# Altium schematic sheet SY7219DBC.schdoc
size 127 x 101 mm
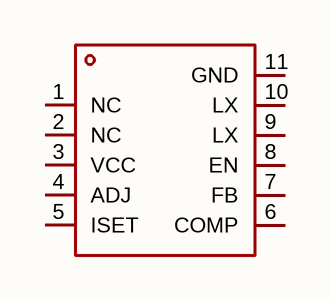
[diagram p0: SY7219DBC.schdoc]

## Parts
U?  sy7219dbc  [DFN-10_L3.0-W3.0-P0.50-TL-EP2.4]  (value not drawn)

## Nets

Not connected (* = marked no-connect by the designer): U? 1(NC) 2(NC) 3(VCC) 4(ADJ) 5(ISET) 6(COMP) 7(FB) 8(EN) 9(LX) 10(LX) 11(GND)

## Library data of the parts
U? = sy7219dbc: 功能类型:升压型;工作电压:3V~5.5V;输出电压:-;输出电流:9A;输出类型:可调;; Manufacturer: Silergy(矽力杰); AddInBom: yes; ModelId: cf917ac8ec364cce99d388f0d060e989; ModelTransform: 118.8974,118.11,0,0,0,0,0,0,0; Function: 升压型; Output Current: 9A; Synchronous Rectifier: 是; Number of Outputs: 1; Topology: 升压式; Quiescent Current: 380uA; Switch tube (built-in/external): 内置; Output Type: 可调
